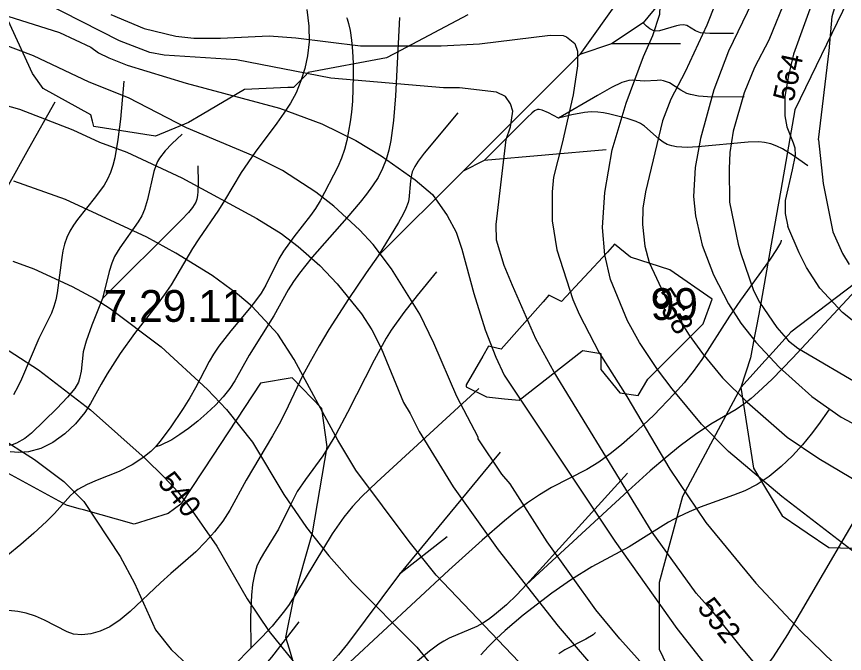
# Model space of a CAD drawing. Extents: x -709584 to -702006, y -1161789 to -1157496.
# Drawn here: x -707587.5 to -707197.2, y -1158614.4 to -1158314.1 of the extents above; entities that cross this region are included whole.
import ezdxf

# ---------------------------------------------------------------- set-up
doc = ezdxf.new("R2010")
doc.units = 0
for name, color, linetype in [('120_vrstevnice hlavní', 7, 'Continuous'), ('121_vrstevnice hlavní_popis', 7, 'Continuous'), ('122_vrstevnice základní', 7, 'Continuous'), ('408_BPEJ_linie', 7, 'Continuous'), ('409_BPEJ_popis', 7, 'Continuous'), ('411_akumulovaný odtok', 7, 'Continuous')]:
    doc.layers.add(name, color=color, linetype=linetype)

msp = doc.modelspace()

# ---------------------------------------------------------------- linework, layer by layer
at = {"layer": '120_vrstevnice hlavní'}
for points in [[(-707236.43, -1158298.41), (-707251.86, -1158330.41), (-707258.72, -1158348.7), (-707265, -1158371.56), (-707267.58, -1158385.27), (-707268.29, -1158398.99), (-707267.43, -1158408.13), (-707264.29, -1158421.84), (-707258.86, -1158435.84), (-707251.86, -1158449.56), (-707246, -1158458.7), (-707239, -1158467.7), (-707228, -1158479.42), (-707212.57, -1158493.28), (-707198.71, -1158502.99), (-707181.57, -1158512.13)], [(-707600.73, -1158311.12), (-707567.3, -1158321.55), (-707552.45, -1158328.55), (-707548.88, -1158331.13), (-707544.02, -1158333.55), (-707535.3, -1158336.98)], [(-707535.3, -1158336.98), (-707507.59, -1158345.55), (-707463.58, -1158357.27), (-707443.58, -1158364.7), (-707427.58, -1158372.56), (-707415.58, -1158379.84), (-707399.58, -1158391.13), (-707391.44, -1158397.99), (-707384.44, -1158407.84), (-707380.3, -1158415.84), (-707377.58, -1158423.84), (-707371.87, -1158444.7), (-707366.58, -1158461.85), (-707361.58, -1158474.7), (-707357.58, -1158483.28), (-707305.43, -1158561.56), (-707276.15, -1158602.71), (-707265.15, -1158616.71), (-707239.15, -1158648.14), (-707229.29, -1158658.71), (-707214.29, -1158673.71), (-707201.29, -1158684.57), (-707188.14, -1158694)], [(-707599.59, -1158466.28), (-707577.16, -1158480.7), (-707552.59, -1158499.56), (-707526.87, -1158522.56), (-707518.02, -1158531.14), (-707511.3, -1158538.42), (-707505.73, -1158545.56), (-707493.01, -1158563.85), (-707478.73, -1158588.71), (-707468.44, -1158604.14), (-707457.01, -1158618.14)]]:
    msp.add_lwpolyline(points, dxfattribs=at)
at = {"layer": '122_vrstevnice základní'}
for points in [[(-707209.43, -1158372.27), (-707204.29, -1158330.28), (-707202.86, -1158314.12), (-707198.43, -1158298.12), (-707194.86, -1158288.12), (-707187, -1158270.12), (-707174.14, -1158246.12), (-707166.86, -1158230.41), (-707155.71, -1158199.55), (-707150.57, -1158180.69), (-707144.71, -1158151.55), (-707141.28, -1158127.26), (-707139.43, -1158103.26), (-707139.43, -1158095.26), (-707141, -1158071.26), (-707141.57, -1158047.26), (-707143.28, -1158027.25), (-707147, -1158007.25), (-707150.85, -1157993.25)], [(-707195.43, -1158208.41), (-707199.43, -1158232.41), (-707202.29, -1158243.26), (-707205.86, -1158252.98), (-707209, -1158265.27), (-707210.86, -1158269.98), (-707214.29, -1158282.41), (-707218.57, -1158292.7), (-707224.43, -1158304.7), (-707232.86, -1158325.27), (-707239.57, -1158338.13), (-707244.43, -1158350.13), (-707249.57, -1158368.13), (-707251.15, -1158378.13), (-707251.57, -1158385.84), (-707251.29, -1158401.56), (-707247.29, -1158421.42), (-707246, -1158425.84), (-707240, -1158443.27), (-707237.15, -1158448.84), (-707229, -1158460.7), (-707223.57, -1158466.99), (-707219.14, -1158470.42), (-707187.57, -1158488.99)], [(-707190, -1158245.84), (-707221.14, -1158331.84), (-707223.57, -1158341.84), (-707225.29, -1158351.84), (-707225.29, -1158360.98), (-707224.29, -1158366.13), (-707221.29, -1158373.7), (-707220.62, -1158376.03), (-707220.34, -1158379.38), (-707221.74, -1158386.36), (-707225.09, -1158400.88), (-707225.09, -1158407.03), (-707223.86, -1158413.13)], [(-707189.86, -1158568.71), (-707226.72, -1158540.42), (-707251.86, -1158519.13), (-707264.58, -1158506.28), (-707278.43, -1158489.71), (-707285.29, -1158480.56), (-707293.72, -1158467.85), (-707299.43, -1158457.56), (-707307.43, -1158438.13), (-707310.15, -1158426.42), (-707311.29, -1158413.56), (-707310.15, -1158396.99), (-707306.72, -1158376.99), (-707300.01, -1158354.98), (-707291.86, -1158332.98), (-707287.43, -1158322.98), (-707284.15, -1158312.98), (-707284, -1158309.41), (-707286.43, -1158304.7), (-707290.01, -1158300.7), (-707294.43, -1158296.98), (-707298.43, -1158295.12)], [(-707254.15, -1158298.12), (-707262, -1158318.12), (-707272.29, -1158340.13), (-707279, -1158352.98), (-707282.86, -1158363.27), (-707291.01, -1158396.7), (-707292.15, -1158404.42), (-707292.29, -1158412.13), (-707291.29, -1158422.42), (-707289.15, -1158430.13), (-707281.15, -1158447.27), (-707270.43, -1158464.42), (-707264.15, -1158472.99), (-707254.72, -1158484.42), (-707243, -1158495.99), (-707224.14, -1158512.42)], [(-707218, -1158644.71), (-707245.72, -1158611.71), (-707259.01, -1158595.05), (-707267, -1158586), (-707287.86, -1158557.28), (-707334.01, -1158481.85), (-707342.72, -1158466.13), (-707353.72, -1158440.99), (-707357.58, -1158431.56), (-707361.15, -1158419.56), (-707361.29, -1158412.13), (-707356.72, -1158372.13), (-707354.58, -1158366.13), (-707353.44, -1158358.7), (-707354.58, -1158355.27), (-707357.01, -1158351.84), (-707361.16, -1158349.8), (-707378.72, -1158347.7), (-707386.15, -1158347.7), (-707439.3, -1158343.13), (-707483.87, -1158334.55), (-707517.87, -1158332.27), (-707524.73, -1158330.98), (-707539.02, -1158325.55), (-707574.73, -1158307.27)], [(-707543.02, -1158313.12), (-707527.3, -1158319.7), (-707512.44, -1158323.27), (-707503.87, -1158324.27), (-707491.3, -1158324.27), (-707468.44, -1158323.12), (-707455.87, -1158324.12), (-707425.3, -1158327.84), (-707387.3, -1158327.84), (-707369.3, -1158326.98), (-707335.86, -1158322.84), (-707329.73, -1158323.09), (-707328.15, -1158323.7), (-707324.29, -1158326.84), (-707323.01, -1158330.41), (-707323.01, -1158337.27), (-707325.01, -1158350.98), (-707330.29, -1158373.84), (-707334.29, -1158389.84), (-707335.01, -1158396.7), (-707335.01, -1158410.42), (-707332.72, -1158424.13), (-707325.15, -1158447.56), (-707322.29, -1158454.42), (-707312.86, -1158472.7), (-707299.72, -1158493.28), (-707279.43, -1158527.56), (-707262.58, -1158552.71), (-707238.86, -1158581.28), (-707217.86, -1158603.85), (-707202.14, -1158619)], [(-707280, -1158633.28), (-707303.01, -1158607.57), (-707314.43, -1158593.85), (-707337.29, -1158561.85), (-707354.72, -1158534.42), (-707358.72, -1158529.85), (-707369.87, -1158513.28), (-707369.87, -1158512.42), (-707379.87, -1158493.28), (-707390.72, -1158468.13), (-707397.3, -1158454.42), (-707410.73, -1158432.99), (-707419.3, -1158421.56), (-707425.87, -1158414.7), (-707437.87, -1158403.56), (-707446.44, -1158396.84), (-707462.16, -1158386.7), (-707476.01, -1158379.84), (-707507.3, -1158366.55), (-707534.73, -1158352.41), (-707553.3, -1158344.98), (-707579.59, -1158332.55), (-707593.59, -1158327.27)], [(-707614.45, -1158349.98), (-707586.16, -1158357.84), (-707561.02, -1158367.55), (-707548.45, -1158373.27), (-707535.45, -1158377.99), (-707509.59, -1158390.13), (-707474.16, -1158409.27), (-707462.73, -1158416.42), (-707454.73, -1158422.56), (-707444.44, -1158431.56), (-707436.3, -1158440.13), (-707424.87, -1158454.27), (-707420.01, -1158461.85), (-707415.58, -1158470.42), (-707405.01, -1158496.13), (-707401.87, -1158501.28), (-707397.72, -1158509.85), (-707381.58, -1158535.85), (-707360.44, -1158565.56), (-707332.15, -1158601.57), (-707310.29, -1158627)], [(-707209.43, -1158372.27), (-707207.11, -1158392.82), (-707202.57, -1158415.56), (-707198.14, -1158425.84), (-707195, -1158430.99)], [(-707196.43, -1158751), (-707214.43, -1158743), (-707225.72, -1158734.43), (-707234.57, -1158726.57), (-707275.72, -1158686.14), (-707295.72, -1158667.71), (-707316.58, -1158650), (-707350.72, -1158618.43), (-707389.72, -1158577.57), (-707402.44, -1158561.71), (-707427.58, -1158527.99), (-707436.01, -1158513.85), (-707456.58, -1158475.85), (-707464.3, -1158463.85), (-707476.44, -1158450.84), (-707483.3, -1158444.99), (-707495.3, -1158436.27), (-707512.44, -1158425.7), (-707526.16, -1158418.13), (-707564.45, -1158400.41), (-707588.73, -1158391.7)], [(-707182.71, -1158465.99), (-707198.14, -1158453.7), (-707208.71, -1158442.13), (-707215, -1158432.42), (-707218.57, -1158425.56), (-707223.86, -1158413.13)], [(-707589.31, -1158429.42), (-707579.31, -1158433.13), (-707561.3, -1158441.42), (-707550.45, -1158447.27), (-707543.3, -1158451.84), (-707519.3, -1158469.85), (-707497.44, -1158489.99), (-707488.44, -1158499.42), (-707476.3, -1158514.85), (-707461.44, -1158539.56), (-707450.73, -1158554.99), (-707440.3, -1158568.42), (-707429.15, -1158580.99), (-707398.72, -1158611.42), (-707386.79, -1158626.05), (-707373.3, -1158639.57), (-707362.29, -1158649.43)], [(-707633.59, -1158491.99), (-707597.02, -1158511.71), (-707579.02, -1158522.99), (-707565.16, -1158533.28), (-707555.73, -1158542.85), (-707538.59, -1158568.71), (-707531.87, -1158581.28), (-707522.02, -1158603.28), (-707514.59, -1158612.57), (-707503.87, -1158622.57), (-707484.87, -1158637), (-707469.01, -1158645.43), (-707460.44, -1158651), (-707449.01, -1158657.28), (-707440.58, -1158663.71), (-707435.01, -1158670), (-707431.87, -1158676.28)], [(-707224.14, -1158512.42), (-707209.29, -1158522.56), (-707184.14, -1158537.42)]]:
    msp.add_lwpolyline(points, dxfattribs=at)
at = {"layer": '408_BPEJ_linie'}
for points in [[(-707195.5, -1158306.5), (-707220.5, -1158358), (-707227.18, -1158396.03), (-707231.16, -1158418.72), (-707237, -1158452), (-707238.44, -1158459.36), (-707239.65, -1158465.56), (-707241.5, -1158475), (-707246, -1158489)], [(-707374.72, -1158313.2), (-707406.54, -1158330.08), (-707413, -1158333.5), (-707450, -1158340.5), (-707451.49, -1158341.99), (-707457, -1158347.5), (-707459.66, -1158347.61), (-707480, -1158348.5), (-707500, -1158360.2), (-707506.5, -1158364), (-707522, -1158370.5), (-707551, -1158366), (-707551.68, -1158363.49), (-707552.5, -1158360.5), (-707575, -1158348), (-707580, -1158341), (-707591.5, -1158316)], [(-707279.48, -1158433.51), (-707279.5, -1158433.5), (-707298, -1158427.5), (-707305.5, -1158421.5), (-707308.87, -1158425.14), (-707330.5, -1158448.5), (-707330.86, -1158448.32), (-707336.5, -1158445.5), (-707339.23, -1158448.59), (-707359, -1158471), (-707361.04, -1158470.49), (-707365, -1158469.5), (-707367.72, -1158474.19), (-707375.58, -1158487.78), (-707375.58, -1158488.71), (-707366, -1158493.5), (-707357.49, -1158494.32), (-707350.5, -1158495), (-707320.94, -1158471.84), (-707320.5, -1158471.5), (-707312, -1158473), (-707312, -1158480.5), (-707303, -1158491.5), (-707294.48, -1158492.84), (-707289.91, -1158485.12), (-707263.78, -1158459.01), (-707259.53, -1158447.31), (-707279.48, -1158433.51)], [(-707175, -1158427), (-707180.85, -1158431.43), (-707187.82, -1158436.71), (-707222.5, -1158463), (-707230.79, -1158472.17), (-707234.48, -1158476.26), (-707246, -1158489)], [(-707456.5, -1158620.5), (-707458.89, -1158612.42), (-707460.5, -1158607), (-707457, -1158589), (-707448, -1158557.5), (-707441, -1158517), (-707443.5, -1158499), (-707457.5, -1158484.5), (-707472.5, -1158487), (-707499.04, -1158527.34), (-707500, -1158528.8), (-707510, -1158544), (-707516, -1158548.5), (-707532, -1158553.5), (-707555.94, -1158546.77), (-707557.98, -1158546.19), (-707564, -1158544.5), (-707609, -1158520)], [(-707246, -1158489), (-707273.5, -1158540.5), (-707284.5, -1158581), (-707284.5, -1158608.53), (-707284.5, -1158612.36), (-707284.5, -1158612.5), (-707269.5, -1158644), (-707264.07, -1158649.58), (-707259.91, -1158653.84), (-707257.73, -1158656.09), (-707251, -1158663), (-707225.5, -1158680), (-707215.41, -1158683.7), (-707211.75, -1158685.04), (-707210.5, -1158685.5)], [(-707246, -1158489), (-707240, -1158527), (-707226.5, -1158549.5), (-707218.23, -1158555.14), (-707218.22, -1158555.14), (-707214.71, -1158557.54), (-707204.5, -1158564.5), (-707188, -1158565)]]:
    msp.add_lwpolyline(points, dxfattribs=at)
at = {"layer": '411_akumulovaný odtok'}
for p, q in [((-707296.99, -1158297), (-707321.99, -1158332)), ((-707291.99, -1158317), (-707306.99, -1158327)), ((-707306.99, -1158327), (-707321.99, -1158332)), ((-707274.49, -1158327), (-707306.99, -1158327)), ((-707321.99, -1158332), (-707376.99, -1158387)), ((-707309.49, -1158377), (-707366.99, -1158382)), ((-707366.99, -1158382), (-707376.99, -1158387)), ((-707376.99, -1158387), (-707416.99, -1158427)), ((-707359.49, -1158519.5), (-707406.99, -1158577)), ((-707299.49, -1158529.5), (-707346.99, -1158582)), ((-707384.49, -1158559.5), (-707406.99, -1158577))]:
    msp.add_line(p, q, dxfattribs=at)
for points in [[(-707219.49, -1158284.5), (-707221.34, -1158282.6), (-707222.66, -1158281.52), (-707224.26, -1158280.43), (-707226.07, -1158279.48), (-707228.07, -1158278.77), (-707230.15, -1158278.34), (-707232.2, -1158278.17), (-707234.11, -1158278.2), (-707237.62, -1158278.61), (-707249.99, -1158280.65), (-707255.2, -1158281.85), (-707259.82, -1158283.53), (-707262.63, -1158284.93), (-707265.31, -1158286.55), (-707267.9, -1158288.58), (-707270.4, -1158291.03), (-707275.06, -1158296.37), (-707291.99, -1158317)], [(-707450.6, -1158310.75), (-707449.66, -1158318.57), (-707449.58, -1158325.98), (-707450.31, -1158332.58), (-707451.63, -1158338.59), (-707453.41, -1158344.44), (-707455.73, -1158350.07), (-707458.38, -1158354.97), (-707461.43, -1158359.69), (-707464.73, -1158364.31), (-707475.04, -1158378.06), (-707481.6, -1158387.69), (-707489.44, -1158400.83), (-707492.34, -1158405.38), (-707501.53, -1158418.87), (-707504.49, -1158423.45), (-707514.63, -1158440.56), (-707517.85, -1158445.29), (-707521.25, -1158449.92), (-707531.9, -1158463.63), (-707538.65, -1158472.98), (-707544.79, -1158482.6), (-707547.65, -1158487.48), (-707552.64, -1158496.57), (-707555.37, -1158500.84), (-707559.69, -1158506.13), (-707564.76, -1158510.92), (-707570.33, -1158514.9), (-707576.14, -1158517.8), (-707581.91, -1158519.39), (-707586.5, -1158519.7), (-707590.58, -1158519.32)], [(-707431.99, -1158314.5), (-707431.6, -1158315.22), (-707430.95, -1158317.36), (-707430.21, -1158320.71), (-707429.55, -1158325.16), (-707429.08, -1158330.4), (-707428.8, -1158336.16), (-707428.72, -1158342.19), (-707429.1, -1158353.97), (-707429.54, -1158359.19), (-707430.13, -1158363.76), (-707431.73, -1158372.55), (-707432.83, -1158376.8), (-707434.22, -1158380.91), (-707436, -1158384.96), (-707444.28, -1158401.05), (-707446.5, -1158404.56), (-707448.94, -1158407.97), (-707456.73, -1158418), (-707461.63, -1158424.8), (-707463.77, -1158428.33), (-707469.94, -1158440.76), (-707472.25, -1158444.51), (-707474.84, -1158448.16), (-707477.62, -1158451.73), (-707486.46, -1158462.27), (-707492.13, -1158469.48), (-707494.69, -1158473.26), (-707496.69, -1158476.71), (-707503.18, -1158489.19), (-707505.78, -1158493.84), (-707508.89, -1158498.91), (-707515.08, -1158508.03), (-707519.95, -1158514.55), (-707521.99, -1158517)], [(-707406.99, -1158314.5), (-707408.83, -1158351.5), (-707409.75, -1158363.03), (-707410.33, -1158367.81), (-707411.06, -1158372.47), (-707412.01, -1158377.04), (-707413.25, -1158381.49), (-707414.89, -1158385.77), (-707417.05, -1158389.93), (-707419.61, -1158393.93), (-707422.43, -1158397.82), (-707425.45, -1158401.62), (-707431.82, -1158409.07), (-707448.1, -1158427.57), (-707454.16, -1158435.15), (-707456.95, -1158439.04), (-707459.49, -1158443.04), (-707466.17, -1158455.16), (-707477.88, -1158473.85), (-707484.58, -1158485.88), (-707486.99, -1158489.5), (-707490.11, -1158493.35), (-707493.78, -1158497.28), (-707497.83, -1158501.18), (-707502.09, -1158504.9), (-707506.38, -1158508.3), (-707510.53, -1158511.25), (-707514.37, -1158513.65), (-707519.75, -1158516.33), (-707521.35, -1158516.92), (-707521.99, -1158517)], [(-707249.49, -1158322), (-707260.58, -1158322.07), (-707265.04, -1158321.69), (-707267.42, -1158320.84), (-707271.53, -1158318.29), (-707273.04, -1158317.95), (-707274.69, -1158318.07), (-707276.41, -1158318.47), (-707284.29, -1158320.88), (-707286.11, -1158321.01), (-707287.1, -1158320.79), (-707288.92, -1158319.84), (-707290.48, -1158318.57), (-707291.99, -1158317)], [(-707244.49, -1158352), (-707259.57, -1158352.1), (-707266.04, -1158351.66), (-707269.68, -1158350.92), (-707271.39, -1158350.32), (-707274.26, -1158348.78), (-707279.67, -1158345.39), (-707282.42, -1158344.34), (-707283.92, -1158344.16), (-707285.46, -1158344.18), (-707291.63, -1158344.63), (-707297.27, -1158344.03), (-707298.83, -1158344.21), (-707302.05, -1158345.18), (-707306.97, -1158347.51), (-707313.62, -1158351.24), (-707331.99, -1158362)], [(-707536.99, -1158344.5), (-707538.57, -1158362.5), (-707539.7, -1158372.13), (-707541.18, -1158380.79), (-707542.09, -1158384.3), (-707543.2, -1158387.61), (-707544.6, -1158390.78), (-707546.27, -1158393.68), (-707550.23, -1158399.17), (-707558.78, -1158409.79), (-707560.71, -1158412.53), (-707562.43, -1158415.35), (-707563.85, -1158418.3), (-707564.9, -1158421.36), (-707565.67, -1158424.53), (-707566.23, -1158427.79), (-707568.29, -1158444.44), (-707568.96, -1158447.68), (-707569.86, -1158450.83), (-707571.07, -1158453.9), (-707577.06, -1158465.95), (-707585.11, -1158485.16), (-707586.86, -1158488.71), (-707588.98, -1158492.44)], [(-707569.49, -1158354.5), (-707581.88, -1158376.47), (-707591.44, -1158393.8)], [(-707379.49, -1158359.5), (-707395.3, -1158378.57), (-707398.07, -1158382.22), (-707399.68, -1158384.73), (-707400.92, -1158387.38), (-707401.31, -1158388.74), (-707401.77, -1158391.57), (-707402.61, -1158400.32), (-707402.92, -1158401.73), (-707403.89, -1158404.54), (-707405.17, -1158407.25), (-707407.39, -1158411.24), (-707416.99, -1158427)], [(-707331.99, -1158362), (-707336.73, -1158359.43), (-707339.63, -1158358.19), (-707341.13, -1158357.93), (-707341.83, -1158357.99), (-707343.26, -1158358.61), (-707344.62, -1158359.64), (-707346.61, -1158361.49), (-707366.99, -1158382)], [(-707214.49, -1158384.5), (-707221.26, -1158379.56), (-707226.36, -1158376.5), (-707229.09, -1158375.17), (-707231.83, -1158374.14), (-707234.77, -1158373.44), (-707237.45, -1158373.19), (-707242.61, -1158373.29), (-707266.27, -1158375.55), (-707271.38, -1158375.79), (-707276.28, -1158375.54), (-707278.58, -1158375.12), (-707280.74, -1158374.38), (-707282.67, -1158373.3), (-707284.48, -1158371.94), (-707291.43, -1158365.77), (-707293.32, -1158364.5), (-707295.31, -1158363.53), (-707299.6, -1158362.17), (-707308.38, -1158359.99), (-707310.76, -1158359.46), (-707313.4, -1158359.12), (-707316.5, -1158359.09), (-707319.69, -1158359.35), (-707325.71, -1158360.39), (-707331.99, -1158362)], [(-707509.49, -1158369.5), (-707514.27, -1158374.12), (-707517.41, -1158377.46), (-707520.13, -1158380.89), (-707521.08, -1158382.48), (-707521.74, -1158383.97), (-707522.76, -1158387.12), (-707525.71, -1158400.31), (-707527.13, -1158405.12), (-707528.46, -1158408.12), (-707530.13, -1158410.94), (-707538.8, -1158423.09), (-707541.33, -1158427.31), (-707542.65, -1158430.44), (-707543.87, -1158434.33), (-707546.99, -1158447)], [(-707501.99, -1158384.5), (-707501.8, -1158392.51), (-707501.97, -1158396.65), (-707502.19, -1158398.54), (-707502.54, -1158400.18), (-707503.04, -1158401.57), (-707504.56, -1158404.12), (-707506.5, -1158406.5), (-707509.75, -1158409.93), (-707546.99, -1158447)], [(-707226.99, -1158419.5), (-707226.94, -1158419.88), (-707227.31, -1158420.83), (-707229.12, -1158423.91), (-707232.22, -1158428.44), (-707246.21, -1158447.81), (-707251.31, -1158455.31), (-707264.35, -1158475.89), (-707268.42, -1158481.45), (-707272.78, -1158486.8), (-707277.37, -1158492.01), (-707287, -1158502.04), (-707297.08, -1158511.54), (-707302.27, -1158516.03), (-707307.58, -1158520.27), (-707313.03, -1158524.2), (-707318.67, -1158527.7), (-707335.29, -1158536.16), (-707341.01, -1158539.6), (-707346.58, -1158543.43), (-707352.05, -1158547.54), (-707357.43, -1158551.87), (-707368.03, -1158560.95), (-707383.71, -1158575.13), (-707476.99, -1158662)], [(-707174.49, -1158424.5), (-707221.65, -1158475.24), (-707231.23, -1158485.07), (-707237.78, -1158491.27), (-707241.15, -1158494.17), (-707244.62, -1158496.88), (-707248.21, -1158499.34), (-707260.11, -1158506.24), (-707267.45, -1158511.21), (-707274.65, -1158516.59), (-707281.72, -1158522.28), (-707288.75, -1158528.33), (-707299.13, -1158537.68), (-707346.99, -1158582)], [(-707416.99, -1158427), (-707422.64, -1158434.99), (-707430.76, -1158446.98), (-707440.21, -1158461.7), (-707444.86, -1158469.4), (-707449.14, -1158476.94), (-707452.61, -1158483.6), (-707460.91, -1158500.85), (-707463.75, -1158506.36), (-707466.78, -1158511.81), (-707479.22, -1158532.73), (-707486.93, -1158546.86), (-707490.32, -1158552.02), (-707494.21, -1158557.02), (-707498.49, -1158561.84), (-707503.05, -1158566.46), (-707507.84, -1158570.84), (-707514.82, -1158576.75), (-707519.71, -1158581.19), (-707533.91, -1158594.72), (-707538.68, -1158598.66), (-707543.58, -1158601.89), (-707548.04, -1158603.95), (-707552.5, -1158605.24), (-707556.77, -1158605.73), (-707560.66, -1158605.36), (-707563.7, -1158604.28), (-707574.28, -1158598.73), (-707578.51, -1158596.89), (-707582.96, -1158595.48), (-707586.93, -1158594.7), (-707591.27, -1158594.19)], [(-707389.49, -1158434.5), (-707398.66, -1158445.62), (-707404.95, -1158453.7), (-707410.84, -1158461.98), (-707413.24, -1158465.8), (-707418.95, -1158476.2), (-707431.47, -1158500.82), (-707437.03, -1158511.22), (-707441.01, -1158517.95), (-707443.14, -1158521.21), (-707451.33, -1158532.41), (-707455.13, -1158538.12), (-707458.23, -1158543.98), (-707464.05, -1158555.89), (-707471.15, -1158567.35), (-707472.78, -1158570.23), (-707474.17, -1158573.24), (-707475.38, -1158577.27), (-707476.23, -1158581.94), (-707476.78, -1158586.99), (-707477.22, -1158597.21), (-707476.99, -1158612)], [(-707546.99, -1158447), (-707552.06, -1158459.6), (-707554.75, -1158467.1), (-707556.06, -1158472.25), (-707557.1, -1158481.35), (-707557.77, -1158484.83), (-707558.34, -1158486.47), (-707560.02, -1158489.46), (-707563.41, -1158493.59), (-707568.52, -1158498.86), (-707580.41, -1158510.49), (-707583.55, -1158513.02), (-707587.48, -1158515.27), (-707589.56, -1158516.08), (-707593.16, -1158516.88), (-707595.89, -1158517.07), (-707596.99, -1158517)], [(-707369.49, -1158489.5), (-707417.68, -1158533.64), (-707424.72, -1158540.41), (-707429.18, -1158545.12), (-707433.25, -1158550.11), (-707438.68, -1158558.1), (-707455.44, -1158585.8), (-707459.36, -1158591.77), (-707461.79, -1158595.11), (-707466.97, -1158601.5), (-707471.84, -1158606.84), (-707476.99, -1158612)], [(-707204.49, -1158499.5), (-707209.34, -1158506.46), (-707212.79, -1158510.96), (-707216.95, -1158516), (-707221.71, -1158521.24), (-707226.96, -1158526.34), (-707232.57, -1158530.95), (-707238.35, -1158534.74), (-707244.07, -1158537.68), (-707249.42, -1158539.83), (-707265.17, -1158545.49), (-707270.32, -1158547.59), (-707275.33, -1158549.96), (-707280.09, -1158552.6), (-707298.63, -1158564.19), (-707316.33, -1158573.63), (-707325.85, -1158579.53), (-707335.11, -1158585.99), (-707348.58, -1158596.37), (-707357.2, -1158603.7), (-707361.34, -1158607.53), (-707365.05, -1158611.23), (-707368.6, -1158615.06)], [(-707521.99, -1158517), (-707524.24, -1158519.25), (-707527.89, -1158522.19), (-707533.05, -1158525.53), (-707539.11, -1158528.59), (-707549.55, -1158532.73), (-707554.25, -1158534.75), (-707558.62, -1158537.17), (-707560.6, -1158538.62), (-707562.15, -1158540.03), (-707569.62, -1158548.38), (-707573.41, -1158552.17), (-707579.38, -1158557.69), (-707585.48, -1158563.06), (-707591.63, -1158568.17)], [(-707179.49, -1158529.5), (-707224.01, -1158605.53), (-707230.72, -1158616.07), (-707235.63, -1158622.69), (-707238.33, -1158625.76), (-707241.23, -1158628.61), (-707247.52, -1158633.84), (-707254.18, -1158638.73), (-707267.83, -1158648.21), (-707274.53, -1158653.05), (-707277.78, -1158655.55), (-707287.53, -1158663.66), (-707291.24, -1158666.25), (-707295.06, -1158668.4), (-707298.87, -1158669.85), (-707302.54, -1158670.41), (-707305.47, -1158670.14), (-707308.04, -1158669.42), (-707310.08, -1158668.49), (-707311.44, -1158667.62), (-707311.99, -1158667)], [(-707406.99, -1158577), (-707431.46, -1158609.88), (-707435.72, -1158615.16), (-707438.57, -1158618.29), (-707442.9, -1158622.25), (-707446, -1158624.47), (-707449.32, -1158626.13), (-707456.24, -1158628.75), (-707458.07, -1158629.74), (-707461.53, -1158632.16), (-707464.85, -1158634.95), (-707469.67, -1158639.5), (-707486.99, -1158657)], [(-707346.99, -1158582), (-707351.69, -1158586.83), (-707356.52, -1158591.44), (-707362.09, -1158596.24), (-707364.94, -1158598.4), (-707367.72, -1158600.23), (-707370.45, -1158601.67), (-707383.59, -1158607.28), (-707386.09, -1158608.62), (-707388.39, -1158610.09), (-707392.77, -1158613.39), (-707401.25, -1158620.37)], [(-707454.49, -1158599.5), (-707467.34, -1158616.14), (-707472.23, -1158621.8), (-707476.74, -1158625.89), (-707485.04, -1158632.7), (-707489.82, -1158636.47), (-707493.41, -1158638.94), (-707495.83, -1158640.06), (-707497.05, -1158640.31), (-707498.27, -1158640.26), (-707499.52, -1158639.97), (-707500.95, -1158639.37), (-707504.18, -1158637.53), (-707511.99, -1158632)], [(-707314.49, -1158604.5), (-707315.67, -1158605.59), (-707319.09, -1158607.68), (-707328.95, -1158612.78), (-707331.79, -1158614.63)], [(-707476.99, -1158612), (-707484.75, -1158619.81), (-707486.52, -1158621.31), (-707487.84, -1158622.16), (-707491.51, -1158623.86), (-707511.99, -1158632)]]:
    msp.add_lwpolyline(points, dxfattribs=at)

# ---------------------------------------------------------------- texts
at = {"layer": '121_vrstevnice hlavní_popis'}
for s, rotation, p in [('564', 77.8219, (-707221.23, -1158354.67)), ('558', 302.0256, (-707288, -1158446.01)), ('540', 308.6859, (-707521.44, -1158533.71)), ('552', 308.4437, (-707266.96, -1158593.02))]:
    msp.add_text(s, height=10, rotation=rotation, dxfattribs=at).set_placement(p)
at = {"layer": '409_BPEJ_popis'}
for s, p in [('99', (-707288.54, -1158457.16)), ('7.29.11', (-707546.47, -1158458.07))]:
    msp.add_text(s, height=15, dxfattribs=at).set_placement(p)

doc.saveas('drawing.dxf')
